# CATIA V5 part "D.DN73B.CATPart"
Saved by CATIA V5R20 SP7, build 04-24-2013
Part number: D.DN73B
Material "Nessuno"
Bounding box of the stored display mesh (mm): x -14.589 to 150.807, y -143.683 to 0, z -91.151 to 75.737
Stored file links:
  C:\Users\designer2\Desktop\Ottobre 2022\25-10-2022\04\Yori Evo 48V\D.DN73B.CATPart
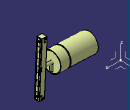
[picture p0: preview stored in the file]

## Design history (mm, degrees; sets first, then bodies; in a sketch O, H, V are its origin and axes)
AxisSystem1: origin (0, 0, 0), X (1, 0, 0), Y (0, 1, 0), Z (0, 0, 1)
Set1
  DatumSurface1
Body1 (main body), material "Nessuno"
